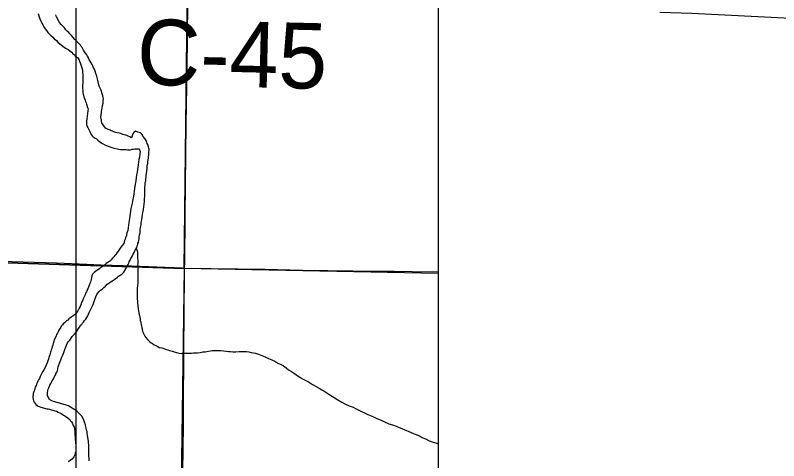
# Model space of a CAD drawing. Extents: x 0 to 68, y 0 to 52.9.
# Drawn here: x 49.378 to 51.122, y 38.666 to 39.684 of the extents above; entities that cross this region are included whole.
import ezdxf

# ---------------------------------------------------------------- set-up
doc = ezdxf.new("R2010")
doc.units = 0
for name, color, linetype in [('Default', 7, 'Continuous'), ('GM_X_County_Road', 7, 'Continuous'), ('GM_X_County_Road_Text', 7, 'Continuous'), ('GM_X_Minor_River', 7, 'Continuous'), ('GM_X_Township_Road', 7, 'Continuous')]:
    doc.layers.add(name, color=color, linetype=linetype)

msp = doc.modelspace()

# ---------------------------------------------------------------- linework, layer by layer
at = {"layer": 'Default'}
for p, q in [((49.5172, 34.4614), (49.5172, 52.9414)), ((50.3451, 32.7683), (50.3451, 42.0083))]:
    msp.add_line(p, q, dxfattribs=at)
for points in [[(48.4787, 40.4689), (49.7795, 40.4261), (49.764, 39.105), (48.4576, 39.1473)], [(49.764, 39.105), (49.7457, 37.7942), (48.4264, 37.8391), (48.4576, 39.1473)]]:
    msp.add_lwpolyline(points, close=True, dxfattribs=at)
for points in [[(50.3451, 39.0938), (49.764, 39.105), (49.7795, 40.4261), (50.3451, 40.4201)], [(49.431, 39.6884), (49.4324, 39.6829), (49.4349, 39.6758), (49.4368, 39.6703), (49.4393, 39.6657), (49.4412, 39.6622), (49.4437, 39.6576), (49.4467, 39.653), (49.4501, 39.649), (49.4531, 39.6444), (49.4571, 39.6398), (49.4605, 39.6368), (49.464, 39.6337), (49.4675, 39.6302), (49.4725, 39.6261), (49.476, 39.6225), (49.48, 39.619), (49.484, 39.6159), (49.4874, 39.6133), (49.4904, 39.6108), (49.4934, 39.6092), (49.4959, 39.6077), (49.4994, 39.6056), (49.5024, 39.6036), (49.5069, 39.6), (49.5109, 39.5954), (49.5134, 39.5934), (49.5154, 39.5909), (49.5179, 39.5888), (49.5204, 39.5873), (49.5233, 39.5837), (49.5282, 39.5706), (49.5301, 39.5641), (49.5316, 39.5585), (49.532, 39.554), (49.5325, 39.549), (49.5324, 39.5439), (49.5328, 39.5389), (49.5328, 39.5344), (49.5327, 39.5294), (49.5321, 39.5238), (49.5321, 39.5178), (49.5325, 39.5128), (49.5324, 39.5073), (49.5334, 39.5037), (49.5344, 39.5012), (49.5353, 39.4977), (49.5368, 39.4936), (49.5378, 39.4901), (49.5392, 39.4866), (49.5402, 39.4841)], [(49.6832, 39.3646), (49.6838, 39.3682), (49.6838, 39.3717), (49.6839, 39.3747), (49.6839, 39.3777), (49.6834, 39.3802), (49.6825, 39.3837), (49.681, 39.3883), (49.68, 39.3913), (49.6791, 39.3938), (49.6771, 39.3979), (49.6741, 39.4024), (49.6707, 39.407), (49.6672, 39.4121), (49.6647, 39.4151), (49.6612, 39.4162), (49.6582, 39.4172), (49.6532, 39.4193), (49.6491, 39.4163), (49.6466, 39.4133), (49.6455, 39.4088), (49.6439, 39.4038), (49.6399, 39.4059), (49.6364, 39.408), (49.6334, 39.4095), (49.6309, 39.41), (49.6274, 39.4111), (49.6244, 39.4116), (49.6214, 39.4127), (49.6184, 39.4137), (49.6154, 39.4143), (49.6114, 39.4153), (49.6078, 39.4164), (49.6033, 39.4179), (49.6003, 39.419), (49.5978, 39.42), (49.5948, 39.4211), (49.5903, 39.4231), (49.5878, 39.4247), (49.5848, 39.4262), (49.5808, 39.4313), (49.5779, 39.4358), (49.5764, 39.4384), (49.5754, 39.4409), (49.575, 39.4444), (49.5745, 39.4479), (49.574, 39.4515), (49.5752, 39.4615), (49.5752, 39.464), (49.5763, 39.468), (49.5768, 39.4725), (49.5779, 39.4775), (49.579, 39.4835), (49.5795, 39.4891), (49.5796, 39.4931), (49.5791, 39.4961), (49.5787, 39.4996), (49.5772, 39.5047), (49.5743, 39.5127), (49.5704, 39.5223), (49.568, 39.5319), (49.5661, 39.539), (49.5646, 39.545), (49.5627, 39.5506), (49.5608, 39.5566), (49.5593, 39.5612), (49.5573, 39.5642), (49.5559, 39.5682), (49.5539, 39.5718), (49.5519, 39.5753), (49.5495, 39.5789), (49.5475, 39.5824), (49.5455, 39.5864), (49.5436, 39.5905), (49.5421, 39.5935), (49.5396, 39.5966), (49.5366, 39.6001), (49.5342, 39.6042), (49.5327, 39.6077), (49.5312, 39.6102), (49.5292, 39.6128), (49.5273, 39.6158), (49.5238, 39.6194), (49.5198, 39.6235), (49.5148, 39.6285), (49.5104, 39.6336), (49.5069, 39.6377), (49.5034, 39.6418), (49.5009, 39.6448), (49.4979, 39.6473), (49.494, 39.6509), (49.4905, 39.655), (49.486, 39.6601), (49.4835, 39.6626), (49.4796, 39.6677), (49.4732, 39.6788), (49.4717, 39.6823), (49.4707, 39.6854)], [(49.5402, 39.4841), (49.5412, 39.481), (49.5422, 39.4785), (49.5436, 39.4735), (49.5446, 39.4704), (49.5445, 39.4659), (49.5434, 39.4594), (49.5423, 39.4534), (49.5418, 39.4474), (49.5412, 39.4419), (49.5411, 39.4373), (49.5411, 39.4343), (49.543, 39.4298), (49.544, 39.4273), (49.546, 39.4242), (49.5475, 39.4212), (49.5489, 39.4181), (49.5499, 39.4146), (49.5519, 39.4116), (49.5539, 39.4085), (49.5563, 39.406), (49.5608, 39.4029), (49.5638, 39.4014), (49.5673, 39.3988), (49.5713, 39.3947), (49.5778, 39.3911), (49.5828, 39.3876), (49.5868, 39.386), (49.5988, 39.3818), (49.6044, 39.3803), (49.6114, 39.3787), (49.6189, 39.3775), (49.626, 39.377), (49.6315, 39.3769), (49.6345, 39.3763), (49.6386, 39.3763), (49.6416, 39.3767), (49.6456, 39.3777), (49.6481, 39.3782), (49.6512, 39.3786), (49.6547, 39.3791), (49.6577, 39.379), (49.6617, 39.3785), (49.6637, 39.3724), (49.6631, 39.3674), (49.662, 39.3599), (49.6609, 39.3544), (49.6599, 39.3484), (49.6588, 39.3424), (49.6582, 39.3369), (49.6576, 39.3318), (49.6566, 39.3258), (49.6555, 39.3193), (49.6544, 39.3123), (49.6538, 39.3053), (49.6522, 39.2983), (49.651, 39.2882), (49.65, 39.2817), (49.6489, 39.2757), (49.6483, 39.2707), (49.6477, 39.2662), (49.6467, 39.2627), (49.6461, 39.2592), (49.6451, 39.2542), (49.644, 39.2486), (49.6424, 39.2421), (49.6391, 39.2196), (49.6385, 39.2151), (49.638, 39.2105), (49.6369, 39.204), (49.6363, 39.198), (49.6352, 39.192), (49.6336, 39.1865), (49.6321, 39.1805), (49.6305, 39.1755), (49.6294, 39.172), (49.6279, 39.169), (49.6263, 39.1625), (49.6222, 39.158), (49.6196, 39.154), (49.6166, 39.1491), (49.6135, 39.1451), (49.6104, 39.1411), (49.6078, 39.1376), (49.6058, 39.1351), (49.6032, 39.1322), (49.6007, 39.1287), (49.5971, 39.1247), (49.5941, 39.1222), (49.5895, 39.1188), (49.5859, 39.1163), (49.5829, 39.1138), (49.5798, 39.1119), (49.5768, 39.1094), (49.5742, 39.1074), (49.5712, 39.105), (49.5686, 39.103), (49.5646, 39.1005), (49.5615, 39.0986), (49.5585, 39.0961), (49.5549, 39.0926)], [(49.5206, 38.9645), (49.5231, 38.968), (49.5257, 38.972), (49.5277, 38.9754), (49.5303, 38.9774), (49.5318, 38.9804), (49.5344, 38.9829), (49.5369, 38.9864), (49.5395, 38.9893), (49.5421, 38.9933), (49.5441, 38.9973), (49.5457, 39.0008), (49.5472, 39.0043), (49.5519, 39.0138), (49.554, 39.0183), (49.5565, 39.0228), (49.5581, 39.0278), (49.5597, 39.0323), (49.5612, 39.0363), (49.5628, 39.0408), (49.5649, 39.0458), (49.5664, 39.0483), (49.569, 39.0522), (49.5731, 39.0557), (49.5771, 39.0582), (49.5807, 39.0621), (49.5843, 39.0651), (49.5884, 39.0691), (49.5924, 39.072), (49.5965, 39.075), (49.5995, 39.077), (49.6031, 39.0789), (49.6066, 39.0814), (49.6117, 39.0853), (49.6143, 39.0878), (49.6178, 39.0898), (49.6219, 39.0922), (49.626, 39.0972), (49.6285, 39.1007), (49.6311, 39.1047), (49.6327, 39.1082), (49.6342, 39.1112), (49.6363, 39.1141), (49.6378, 39.1176), (49.6389, 39.1206), (49.6409, 39.1241), (49.6425, 39.1281), (49.644, 39.1306), (49.6461, 39.1341), (49.6476, 39.1381), (49.6502, 39.1421), (49.6518, 39.1456), (49.6538, 39.1501), (49.6559, 39.1531), (49.6569, 39.1571), (49.658, 39.1601), (49.6585, 39.1631), (49.6596, 39.1656), (49.6606, 39.1696), (49.6612, 39.1731), (49.6617, 39.1771), (49.6623, 39.1821), (49.6634, 39.1871), (49.664, 39.1941), (49.6645, 39.1992), (49.6656, 39.2047), (49.6662, 39.2107), (49.6673, 39.2162), (49.6684, 39.2232), (49.6689, 39.2292), (49.6705, 39.2352), (49.6711, 39.2408), (49.6722, 39.2458), (49.6728, 39.2528), (49.6733, 39.2578), (49.6739, 39.2613), (49.6739, 39.2658), (49.674, 39.2693), (49.6745, 39.2729), (49.6746, 39.2764), (49.6741, 39.2809), (49.6747, 39.2834), (49.6747, 39.2869), (49.6742, 39.2914), (49.6748, 39.2954), (49.6748, 39.299), (49.6754, 39.3015), (49.6764, 39.3045), (49.677, 39.31), (49.6771, 39.315), (49.6776, 39.3185), (49.6782, 39.3225), (49.6793, 39.3341), (49.6799, 39.3391), (49.6804, 39.3426), (49.681, 39.3456), (49.6815, 39.3496), (49.6821, 39.3536), (49.6826, 39.3571), (49.6827, 39.3611), (49.6832, 39.3646)], [(49.5549, 39.0926), (49.5533, 39.0886), (49.5528, 39.0846), (49.5517, 39.0801), (49.5512, 39.0771), (49.5501, 39.0741), (49.5491, 39.0711), (49.5439, 39.0591), (49.5418, 39.0551), (49.5408, 39.0516), (49.5392, 39.0486), (49.5377, 39.0451), (49.5361, 39.0406), (49.5335, 39.0356), (49.532, 39.0316), (49.5299, 39.0281), (49.5289, 39.0246), (49.5278, 39.0221), (49.5263, 39.0182), (49.5247, 39.0142), (49.5216, 39.0087), (49.5191, 39.0052), (49.517, 39.0027), (49.5134, 38.9997), (49.5109, 38.9973), (49.5084, 38.9958), (49.5058, 38.9938), (49.5033, 38.9918), (49.5007, 38.9899), (49.4982, 38.9869), (49.4956, 38.9854), (49.4911, 38.9814), (49.488, 38.979), (49.486, 38.9765), (49.4834, 38.9735), (49.4824, 38.971), (49.4793, 38.9665), (49.4783, 38.964), (49.4762, 38.9605), (49.4746, 38.9576), (49.4726, 38.9541), (49.4715, 38.9511), (49.47, 38.9476), (49.4674, 38.9421), (49.4663, 38.9386), (49.4653, 38.9341), (49.4642, 38.9301), (49.4627, 38.9261), (49.4616, 38.9221), (49.4606, 38.9191), (49.4595, 38.9166), (49.459, 38.9141), (49.4584, 38.9106), (49.4574, 38.9076), (49.4558, 38.9041), (49.4553, 38.9016), (49.4543, 38.8981), (49.4527, 38.8941), (49.4511, 38.8896), (49.449, 38.8846), (49.4465, 38.8791), (49.4439, 38.8736), (49.4408, 38.8691), (49.4392, 38.8661), (49.4377, 38.8626), (49.4356, 38.8581), (49.4336, 38.8541), (49.4315, 38.8506), (49.4299, 38.8477), (49.4284, 38.8442), (49.4268, 38.8412), (49.4258, 38.8377), (49.4242, 38.8342), (49.4232, 38.8307), (49.4221, 38.8272), (49.4206, 38.8242), (49.4195, 38.8197), (49.419, 38.8157), (49.4189, 38.8131), (49.4189, 38.8101), (49.4194, 38.8066), (49.4198, 38.8031), (49.4213, 38.7995), (49.4238, 38.7965), (49.4252, 38.794), (49.4282, 38.7924), (49.4307, 38.7909), (49.4332, 38.7898), (49.4368, 38.7883), (49.4453, 38.7857), (49.4478, 38.7851), (49.4503, 38.7846), (49.4538, 38.7841), (49.4568, 38.7835), (49.4603, 38.7825), (49.4644, 38.7814), (49.4689, 38.7798), (49.4729, 38.7788), (49.4764, 38.7772), (49.4799, 38.7752), (49.4829, 38.7736)], [(49.5475, 38.6658), (49.5471, 38.6698), (49.5471, 38.6728), (49.5466, 38.6764), (49.5462, 38.6799), (49.5462, 38.6829), (49.5463, 38.6869), (49.5463, 38.6904), (49.5464, 38.6939), (49.5464, 38.698), (49.5465, 38.702), (49.546, 38.7065), (49.5456, 38.7105), (49.5451, 38.7145), (49.5437, 38.7246), (49.5428, 38.7286), (49.5423, 38.7327), (49.5413, 38.7357), (49.5404, 38.7402), (49.5394, 38.7437), (49.5385, 38.7478), (49.5365, 38.7538), (49.5351, 38.7589), (49.5336, 38.7624), (49.5307, 38.7675), (49.5272, 38.771), (49.5227, 38.7756), (49.5187, 38.7792), (49.5147, 38.7822), (49.5107, 38.7848), (49.5082, 38.7863), (49.5047, 38.7884), (49.4997, 38.791), (49.4972, 38.792), (49.4932, 38.7936), (49.4892, 38.7946), (49.4837, 38.7957), (49.4797, 38.7973), (49.4767, 38.7983), (49.4742, 38.7989), (49.4711, 38.7994), (49.4686, 38.8004), (49.4656, 38.801), (49.4621, 38.8025), (49.4591, 38.8041), (49.4566, 38.8061), (49.4532, 38.8112), (49.4522, 38.8147), (49.4518, 38.8207), (49.4528, 38.8263), (49.4539, 38.8293), (49.4549, 38.8323), (49.4575, 38.8387), (49.4596, 38.8427), (49.4611, 38.8452), (49.4627, 38.8482), (49.4647, 38.8517), (49.4668, 38.8552), (49.4694, 38.8607), (49.471, 38.8647), (49.473, 38.8682), (49.4746, 38.8717), (49.4756, 38.8757), (49.4767, 38.8802), (49.4783, 38.8852), (49.4793, 38.8892), (49.4809, 38.8927), (49.4824, 38.8967), (49.484, 38.9012), (49.4866, 38.9057), (49.4897, 38.9132), (49.4918, 38.9202), (49.4939, 38.9262), (49.4955, 38.9302), (49.4975, 38.9352), (49.4991, 38.9376), (49.5031, 38.9416), (49.5062, 38.9461), (49.5083, 38.9496), (49.5114, 38.9531), (49.5144, 38.956), (49.5175, 38.96), (49.5206, 38.9645)], [(49.4829, 38.7736), (49.4859, 38.7721), (49.4884, 38.77), (49.4914, 38.7685), (49.4939, 38.7669), (49.4994, 38.7629), (49.5029, 38.7598), (49.5049, 38.7573), (49.5068, 38.7547), (49.5093, 38.7507), (49.5108, 38.7466), (49.5127, 38.7431), (49.5137, 38.7381), (49.5141, 38.732), (49.5145, 38.7265), (49.5155, 38.72), (49.5154, 38.7144), (49.5158, 38.7094), (49.5163, 38.7059), (49.5168, 38.7034), (49.5167, 38.6978), (49.5166, 38.6938), (49.5166, 38.6898), (49.5166, 38.6868), (49.5155, 38.6838), (49.515, 38.6808), (49.5134, 38.6778), (49.5124, 38.6748), (49.5083, 38.6698), (49.5047, 38.6669), (49.5001, 38.6634)]]:
    msp.add_lwpolyline(points, dxfattribs=at)
at = {"layer": 'GM_X_County_Road'}
msp.add_lwpolyline([(50.8504, 39.6914), (50.9236, 39.6891), (51.3006, 39.6695), (52.0217, 39.6321), (52.1863, 39.6234)], dxfattribs=at)
at = {"layer": 'GM_X_Minor_River'}
for points in [[(49.6548, 39.1515), (49.6573, 39.143), (49.6577, 39.138), (49.6577, 39.1345), (49.6576, 39.1314), (49.6576, 39.1274), (49.658, 39.1239), (49.658, 39.1174), (49.6579, 39.1113), (49.6583, 39.1048), (49.6582, 39.0978), (49.6581, 39.0913), (49.658, 39.0837), (49.6585, 39.0772), (49.6584, 39.0717), (49.6578, 39.0656), (49.6572, 39.0601), (49.6572, 39.0541), (49.6571, 39.0476), (49.657, 39.0395), (49.6578, 39.027), (49.6592, 39.0134), (49.6601, 39.0084), (49.661, 39.0028), (49.662, 38.9978), (49.6629, 38.9938), (49.6634, 38.9902), (49.6639, 38.9867), (49.6648, 38.9842), (49.6653, 38.9807), (49.6658, 38.9771), (49.6667, 38.9736), (49.6672, 38.9706), (49.6682, 38.9681), (49.6686, 38.965), (49.6691, 38.9625), (49.6701, 38.96), (49.6715, 38.957), (49.6725, 38.9539), (49.6745, 38.9504), (49.6765, 38.9474), (49.6804, 38.9428), (49.6834, 38.9402), (49.6859, 38.9377), (49.6889, 38.9357), (49.6919, 38.9336), (49.6954, 38.931), (49.6994, 38.929), (49.7039, 38.9269), (49.7074, 38.9249), (49.7129, 38.9238), (49.7174, 38.9222), (49.7219, 38.9206), (49.7265, 38.9196), (49.731, 38.918), (49.7365, 38.9164), (49.7415, 38.9144), (49.747, 38.9133), (49.7531, 38.9117), (49.7586, 38.9111), (49.7636, 38.9116), (49.7707, 38.9115), (49.7757, 38.9119), (49.7808, 38.9118), (49.7853, 38.9123), (49.7898, 38.9127), (49.7949, 38.9127), (49.8004, 38.9136), (49.8065, 38.9145), (49.8125, 38.9149), (49.8282, 38.9177), (49.8357, 38.9181), (49.8418, 38.9181), (49.8478, 38.9175), (49.8543, 38.9169), (49.8604, 38.9163), (49.8654, 38.9157), (49.8699, 38.9152), (49.8755, 38.9151), (49.882, 38.915), (49.8901, 38.9154), (49.8981, 38.9153), (49.9067, 38.9152), (49.9122, 38.9146), (49.9172, 38.9136), (49.9223, 38.9125), (49.9273, 38.9114), (49.9338, 38.9093), (49.9413, 38.9062), (49.9488, 38.9031), (49.9568, 38.8995), (49.9644, 38.8964), (49.9709, 38.8933), (49.9779, 38.8892), (49.9854, 38.886), (49.9909, 38.8825), (49.9969, 38.8784), (50.0028, 38.8738), (50.0093, 38.8697), (50.0158, 38.8656), (50.0218, 38.8615)], [(50.0218, 38.8615), (50.0288, 38.8563), (50.0358, 38.8522), (50.0418, 38.8491), (50.0478, 38.846), (50.0573, 38.8404), (50.0653, 38.8358), (50.0723, 38.8317), (50.0788, 38.8281), (50.0853, 38.824), (50.0923, 38.8198), (50.0988, 38.8152), (50.1068, 38.8101), (50.1153, 38.805), (50.1243, 38.7998), (50.1328, 38.7952), (50.1408, 38.7911), (50.1498, 38.788), (50.1558, 38.7849), (50.1628, 38.7818), (50.1834, 38.7719), (50.1914, 38.7688), (50.1984, 38.7657), (50.2059, 38.7616), (50.2139, 38.7585), (50.2214, 38.7549), (50.2319, 38.7502), (50.2399, 38.7476), (50.248, 38.7445), (50.255, 38.7419), (50.2615, 38.7393), (50.2685, 38.7367), (50.276, 38.7336), (50.284, 38.7299), (50.2916, 38.7268), (50.2976, 38.7242), (50.3031, 38.7221), (50.3076, 38.7186), (50.3166, 38.7149), (50.3241, 38.7113), (50.3451, 38.7041)]]:
    msp.add_lwpolyline(points, dxfattribs=at)
at = {"layer": 'GM_X_Township_Road'}
for points in [[(49.7653, 39.1063), (49.7656, 39.1195), (49.7664, 39.2263), (49.769, 39.4356), (49.7707, 39.5628), (49.7715, 39.6326), (49.7734, 39.7968), (49.7755, 39.9528), (49.7763, 40.0348), (49.7778, 40.2442), (49.7779, 40.3427), (49.7788, 40.4277)], [(49.1342, 39.129), (49.1941, 39.127), (49.2474, 39.1251), (49.3459, 39.1223), (49.4729, 39.1179), (49.5415, 39.1152), (49.5747, 39.1136), (49.6247, 39.1119), (49.7599, 39.1064), (49.7653, 39.1063)], [(49.7623, 38.4494), (49.7624, 38.5084), (49.7617, 38.5946), (49.7613, 38.6397), (49.7616, 38.6931), (49.7624, 38.7464), (49.7623, 38.7996), (49.7632, 38.902), (49.7643, 39.0211), (49.7647, 39.0744), (49.7653, 39.1063)], [(49.7653, 39.1063), (49.9486, 39.1034), (50.0347, 39.1018), (50.207, 39.0995), (50.2439, 39.0991), (50.2849, 39.0982), (50.3451, 39.0973)]]:
    msp.add_lwpolyline(points, dxfattribs=at)

# ---------------------------------------------------------------- texts
at = {"layer": 'GM_X_County_Road_Text'}
msp.add_text('C-45', height=0.15, rotation=358.6526, dxfattribs=at).set_placement((49.6548, 39.5257))

doc.saveas('drawing.dxf')
